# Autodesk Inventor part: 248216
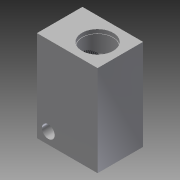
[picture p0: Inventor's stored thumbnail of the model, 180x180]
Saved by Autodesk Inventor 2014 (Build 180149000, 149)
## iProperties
Shininess: 20.0
Length Units: 11272
Angle Units: 11279
Time Units: 11290
Mass Units: 11286
Length Display Precision: 3
Angle Display Precision: 2
Company: Autodesk, Inc.
Created: 2003-01
Part Number: 248216
Material: Steel, Mild
Description: VALVE BODY;A; CAL/S
Document SubType Name: Modeling
Designer: Autodesk, Inc.
Density: 7.86 g/cm^3
Sheet Metal Rule: Default
Mass: 738.798 g
Surface Area: 244.183 cm^2
Volume: 93.9947 cm^3
Appearance: Steel
Density: 0.0
Volumn: 0.0
Area: 0.0
PropertySet Name: Model Information
Control State: 0
Master: False
Checked Out: False
Last Check In By: JT
Last Check In Date: 2003-06-20
Title: VALVE BODY;A; CAL/S
Author: Autodesk, Inc.
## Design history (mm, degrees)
sketch "Sketch1"
  geometry: L1 (0, 0)-(50.8, 0); L2 (50.8, 0)-(50.8, 76.2); L3 (50.8, 76.2)-(0, 76.2); L4 (0, 76.2)-(0, 0); C1 r 5.334 at (9.525, 9.525)
  constraints: 8 end point, 2 parallel, 1 centre point, 1 horizontal, 1 perpendicular
  dimensions: "d3" = 50.8 distance of L1.start L1.end; "d4" = 76.2 distance of L3.end L1.start; "d5" = 9.525 distance from line of L4 C1.centre; "d6" = 9.525 distance from line of L1 C1.centre; "d7" = 10.668 diameter of C1
extrude "Extrusion2" new body sketch "Sketch1" stored distance "d8" = 38.1; taper "d9" = 0 deg
sketch "Sketch2"
  geometry: L1 (50.8, 76.2)-(0, 76.2) reference; L2 (50.8, 0)-(50.8, 76.2) reference; L3 (0, 0)-(50.8, 0) reference; L4 (0, 76.2)-(0, 0) reference; L5 (31.75, 76.2)-(31.75, 0); L6 (44.831, 76.2)-(44.831, 73.025); L7 (44.831, 73.025)-(44.45, 73.025); L8 (44.45, 73.025)-(44.45, 58.786); L9 (44.45, 58.786)-(43.561, 56.978); L10 (43.561, 56.978)-(43.561, 29.551); L11 (43.561, 29.551)-(41.275, 29.551); L12 (41.275, 29.551)-(41.275, 26.981); L13 (41.275, 26.981)-(45.244, 23.012); L14 (45.244, 23.012)-(45.244, 3.302); L15 (45.244, 3.302)-(46.33, 0)
  constraints: 22 end point, 6 parallel, 4 point on line, 2 perpendicular
  dimensions: "d10" = 31.75 distance from line of L5.end L4; "d12" = 29.1592 diameter of L15.end L5; "d13" = 26.9875 diameter of L14 L5; "d14" = 3.302 vertical distance of L14.end L15.end; "d15" = 23.0124 distance from line of L13.end L3; "d16" = 19.05 diameter of L12 L5; "d17" = 45 deg angle of L14 L13; "d29" = 25.4 diameter of L8 L5; "d30" = 23.622 diameter of L10 L5; "d31" = 26.162 diameter of L6 L5; "d32" = 3.175 vertical distance of L5.start L6.end
revolve "Revolution1" sketch "Sketch2" stored, may be unused: angle "d18" = 90 deg
thread "Thread1" dims "d19" = 25.4, "d20" = 0
sketch "Sketch3"
  geometry: L1 (0, 76.2)-(0, 0) reference; L2 (0, 0)-(50.8, 0) reference; L3 (0, 49.276)-(37.111, 49.276); L4 (37.111, 49.276)-(37.111, 38.369); L5 (37.111, 38.369)-(25.211, 38.369); L6 (25.211, 38.369)-(23.012, 35.782); L7 (23.012, 35.782)-(3.302, 35.782); L8 (3.302, 35.782)-(0, 34.696)
  constraints: 12 end point, 3 parallel, 2 point on line, 1 perpendicular
  dimensions: "d21" = 49.276 distance from line of L2 L3.start; "d22" = 29.1592 diameter of L8.end L3; "d23" = 26.9875 diameter of L7 L3; "d24" = 3.302 horizontal distance of L7.end L8.end; "d25" = 23.0124 distance from line of L6.end L1
revolve "Revolution2" sketch "Sketch3" stored, may be unused: angle "d26" = 90 deg
thread "Thread2" dims "d27" = 25.4, "d28" = 0
body "Solid1"
other parameters: "Thickness" = 6.35, "BendRadius" = 6.35, "BendReliefWidth" = 6.35 (= Thickness), "BendReliefDepth" = 3.175 (= 0.5 x Thickness), "CornerReliefSize" = 25.4 (= 4 x Thickness), "SeamGap" = 0.00508, "MinimumRemnant" = 12.7 (= 2 x Thickness), "TransitionRadius" = 6.35 (= BendRadius), "JacobiRadiusSize" = 6.35 (= Thickness), "GapSize" = 6.35 (= Thickness)
